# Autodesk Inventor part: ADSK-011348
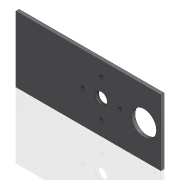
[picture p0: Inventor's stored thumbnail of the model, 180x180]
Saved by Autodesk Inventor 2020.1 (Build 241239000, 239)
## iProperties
Created: 1999-11
Part Number: ADSK-011348
Material: Acier doux
Document SubType Name: Modeling
Designer: glanglot
Density: 7.86 g/cm^3
Appearance: Metal-Steel(Polish)
Mass: 13025.8 g
Surface Area: 2962.35 cm^2
Volume: 1657.23 cm^3
Control State: 0
Master: False
Checked Out: False
Shininess: 0.0
Length Units: 11269
Angle Units: 11279
Time Units: 11290
Mass Units: 11283
Length Display Precision: 5
Angle Display Precision: 5
Compacted: True
Cutlength: 22
Material Desc: FLAT,HRS,0.500X10.000
Material_Number: A084310
Dimensions: 560x254x12,5 mm
Mass: 13,026 kg
Density: 0.0
Volumn: 0.0
Area: 0.0
PropertySet Name: Model Information
Author: glanglot
Revision Number: -
Title: ADSK-011348
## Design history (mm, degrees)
node "Solide1"
  node "Extrusion1" dims "d2" = 12.5, "d3" = 0
  node "Hole1" dims "d14" = 6.6, "d15" = 9.525, "d16" = 6.35, "d17" = 60 deg, "d18" = 19.05, "d19" = 118 deg, "d79" = 6
  node "Hole2" dims "d31" = 45, "d32" = 9.525, "d33" = 6.35, "d34" = 60 deg, "d35" = 19.05, "d36" = 118 deg, "d80" = 6
  node "Hole3" dims "d46" = 13.5, "d47" = 9.525, "d48" = 6.35, "d49" = 60 deg, "d50" = 19.05, "d51" = 118 deg, "d81" = 6
  node "Hole4" dims "d57" = 95, "d58" = 9.525, "d59" = 6.35, "d60" = 60 deg, "d61" = 19.05, "d62" = 118 deg, "d82" = 6
  node "Hole5" dims "d71" = 6.6, "d72" = 9.525, "d73" = 6.35, "d74" = 60 deg, "d75" = 19.05, "d76" = 118 deg, "d83" = 6
sketch "Sketch1"
  geometry: L1 (560, 254)-(0, 254); L2 (0, 254)-(0, 0); L3 (0, 0)-(560, 0); L4 (560, 0)-(560, 254); 1 further point
  constraints: 8 end point, 2 parallel, 1 coincident, 1 horizontal, 1 perpendicular
  dimensions: "d0" = 254 distance of L1.end L2.end; "d1" = 560 distance of L2.end L3.end
sketch "Sketch4"
  geometry: L1 (0, 0)-(0, 254) reference; L2 (25, 235)-(535, 235); L3 (535, 235)-(535, 19); L4 (535, 19)-(25, 19); L5 (25, 19)-(25, 235); L6 (560, 0)-(0, 0) reference; 12 further points
  constraints: 8 end point, 4 coincident, 4 midpoint, 4 point on line, 3 vertical alignment, 2 parallel, 1 horizontal, 1 horizontal alignment, 1 perpendicular
  dimensions: "d77" = 216 distance of L4.end L2.start; "d78" = 510 distance of L2.start L2.end; "d85" = 152.4 distance from line of L5 point (177.4, 235); "d86" = 152.4 distance of point (177.4, 235) point (329.8, 235) (= d85)
sketch "Sketch5"
  geometry: L1 (0, 0)-(0, 254) reference; L2 (560, 254)-(560, 0) reference; 2 further points
  constraints: 1 horizontal alignment, 1 midpoint
  dimensions: "d37" = 330.2 distance from line of point (330.2, 127) L1
sketch "Sketch6"
  geometry: L1 (0, 254)-(560, 254) reference; L2 (258.2, 127)-(330.2, 127); L3 (330.2, 127)-(330.2, 199); L4 (330.2, 55)-(330.2, 127); L5 (402.2, 127)-(330.2, 127); C1 r 22.5 at (330.2, 127) reference; A1 r 72 centre (330.2, 127) between (330.2, 199) and (258.2, 127)
  constraints: 8 end point, 4 point on circle, 3 perpendicular, 1 centre point, 1 coincident
  dimensions: "d53" = 90 deg angle of L1 L3; "d54" = 144 diameter of A1
sketch "Sketch7"
  geometry: L1 (560, 254)-(560, 0) reference; 2 further points
  constraints: 1 horizontal alignment, 1 midpoint
  dimensions: "d55" = 65 distance from line of L1 point (495, 127)
sketch "Sketch8"
  geometry: C1 r 47.5 at (495, 127) reference; 4 further points
  dimensions: "d63" = 38 horizontal distance of C1.centre point (457, 165); "d64" = 38 horizontal distance of C1.centre point (457, 165) (= d63); "d65" = 38 horizontal distance of C1.centre point (533, 165) (= d63); "d66" = 38 horizontal distance of C1.centre point (533, 165) (= d63); "d67" = 38 horizontal distance of point (533, 89) C1.centre (= d63); "d68" = 38 horizontal distance of C1.centre point (533, 89) (= d63); "d69" = 38 horizontal distance of point (457, 89) C1.centre (= d63); "d70" = 38 horizontal distance of C1.centre point (457, 89) (= d63)
node "Corps solides"
node "Corps surfaciques"
